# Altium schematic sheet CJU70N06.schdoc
size 127 x 101 mm
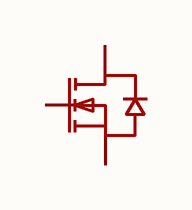
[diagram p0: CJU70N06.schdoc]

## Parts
Q?  cju70n06  [TO-252-3_L6.6-W6.1-P4.57-LS9.9-BR-CW]  (value not drawn)

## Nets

Not connected (* = marked no-connect by the designer): Q? 1(G) 2(D) 3(S)

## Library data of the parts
Q? = cju70n06: 数量:1个N沟道;漏源电压(Vdss):60V;连续漏极电流(Id):70A;导通电阻(RDS(on)):9.5mΩ@10V;耗散功率(Pd):80W;阈值电压(Vgs(th)):1V;; Manufacturer: CJ(江苏长电/长晶); AddInBom: yes; ModelId: dee852f3c6b348a2b9d5be5dd3244081; ModelTransform: 258.97184,390.1567,0,90,0,0,-35.433,0,0; Number: 1个N沟道; Drain to Source Voltage: 60V; Current - Continuous Drain(Id): 70A; Pd - Power Dissipation: 80W; Gate Threshold Voltage (Vgs(th)): 1V; Gate Charge(Qg): 39nC@10V; Input Capacitance(Ciss): 2.15nF; Reverse Transfer Capacitance (Crss@Vds): 80pF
